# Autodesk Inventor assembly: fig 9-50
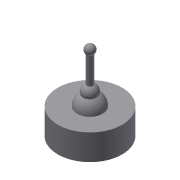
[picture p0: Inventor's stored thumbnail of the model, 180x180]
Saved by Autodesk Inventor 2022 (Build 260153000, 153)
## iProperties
Created: 2013-07
Part Number: fig 9-50
Document SubType Name: Assembly
Designer: CADCIM
Author: CADCIM
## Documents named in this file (3)
- D:\PROJECTS_2021\Resources\Part Files\c09_Inv_2022_prt\fig 9-51.iam
- D:\PROJECTS_2021\Resources\Part Files\c09_Inv_2022_prt\19.ipt
- D:\PROJECTS_2021\Resources\Part Files\c09_Inv_2022_prt\20.ipt
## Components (2 placed, 2 different names)
1. 19:1 — Ball:1
2. 20:1 — Ball:1
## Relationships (1: BallJoint 1)
- Ball:1: 19:1 ↔ 20:1
